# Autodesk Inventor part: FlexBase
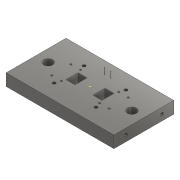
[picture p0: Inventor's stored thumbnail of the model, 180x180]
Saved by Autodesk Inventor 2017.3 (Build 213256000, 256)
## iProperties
Part Number: FlexBase
Material: ステンレス鋼
Document SubType Name: モデリング
Designer: kyushu-hep
Density: 8 g/cm^3
Appearance: 半つや出し
Sheet Metal Rule: Default
Mass: 5352.02 g
Surface Area: 367.335 cm^2
Volume: 277.307 cm^3
Author: kyushu-hep
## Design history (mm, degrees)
sketch "スケッチ1"
  geometry: L1 (-126, 0)-(126, 0) reference; L2 (0, -70)-(0, 70) reference; L3 (90, -50)-(-90, -50); L4 (-90, -50)-(-90, 50); L5 (-90, 50)-(90, 50); L6 (90, 50)-(90, -50); L7 (90, -50)-(-90, 50); L8 (-90, -50)-(90, 50); 1 further point
  constraints: 12 end point, 2 midpoint, 2 parallel, 1 horizontal, 1 perpendicular
  dimensions: "d0" = 180 distance of L4.end L5.end; "d1" = 100 distance of L3.end L4.end
extrude "押し出し1" new body sketch "スケッチ1" distance "d2" = 20; taper "d3" = 0 deg
sketch "スケッチ12"
  geometry: L1 (-90, 50)-(-90, -50) reference; L2 (-90, -50)-(90, -50) reference; C1 r 0.5 at (-5.05, 29.5); C2 r 0.5 at (5.05, 29.5); 1 further point
  constraints: 2 centre point
  dimensions: "d66" = 1 diameter of C1; "d67" = 1 diameter of C2; "d130" = 10.1 distance of C2.centre C1.centre; "d133" = 29.5 vertical distance of point (0, 0) C2.centre; "d134" = 5.05 horizontal distance of C1.centre point (0, 0)
extrude "押し出し9" join sketch "スケッチ12" distance "d72" = 10; taper "d73" = 0 deg
sketch "スケッチ18"
  geometry: L1 (-90, 50)-(-90, -50) reference; L2 (-15, -10)-(-30, -10); L3 (-30, -10)-(-30, 10); L4 (-30, 10)-(-15, 10); L5 (-15, 10)-(-15, -10); L6 (-15, -10)-(-30, 10); L7 (-30, -10)-(-15, 10); L8 (90, -50)-(90, 50) reference; L9 (15, -10)-(30, -10); L10 (30, -10)-(30, 10); L11 (30, 10)-(15, 10); L12 (15, 10)-(15, -10); L13 (15, -10)-(30, 10); L14 (30, -10)-(15, 10); L15 (-90, -50)-(90, -50) reference; 3 further points
  constraints: 24 end point, 4 midpoint, 4 parallel, 2 equal length, 2 horizontal, 2 perpendicular, 1 collinear
  dimensions: "d108" = 15 distance from line of point (0, 0) L5; "d109" = 20 distance of L4.end L2.start; "d135" = 10 distance from line of point (0, 0) L2; "d151" = 15 distance of L2.start L2.end; "d152" = 15 distance from line of L12 point (0, 0)
extrude "押し出し15" cut sketch "スケッチ18" distance "d111" = 30; taper "d112" = 0 deg
sketch "スケッチ22"
  geometry: 1 further point
sketch "スケッチ23"
  geometry: C1 r 7.5 at (-70, 0); C2 r 7.5 at (70, 0); 1 further point
  constraints: 2 centre point
  dimensions: "d181" = 15 diameter of C1; "d184" = 15 diameter of C2; "d200" = 0 vertical distance of point (0, 0) C1.centre; "d201" = 0 vertical distance of C2.centre point (0, 0); "d204" = 70 distance of point (0, 0) C1.centre; "d205" = 70 distance of C2.centre point (0, 0)
sketch "スケッチ24"
  geometry: C1 r 2.5 at (-35, 25); C2 r 2.5 at (35, 25); C3 r 2.5 at (-35, -25); C4 r 2.5 at (35, -25); 2 further points
  constraints: 4 centre point, 1 coincident
  dimensions: "d159" = 5 diameter of C1; "d160" = 25 vertical distance of C1.centre point (0, 0); "d161" = 35 horizontal distance of C1.centre point (0, 0); "d162" = 5 diameter of C2; "d163" = 35 horizontal distance of point (0, 0) C2.centre; "d164" = 25 vertical distance of C2.centre point (0, 0); "d165" = 5 diameter of C3; "d166" = 25 vertical distance of point (0, 0) C3.centre; "d167" = 35 horizontal distance of point (0, 0) C3.centre; "d168" = 5 diameter of C4; "d169" = 25 vertical distance of point (0, 0) C4.centre; "d170" = 35 horizontal distance of point (0, 0) C4.centre
extrude "押し出し19" cut sketch "スケッチ24" distance "d171" = 20; taper "d172" = 0 deg
feature "ねじ4" dims "d173" = 10, "d174" = 0
feature "ねじ5" dims "d175" = 10, "d176" = 0
feature "ねじ6" dims "d177" = 10, "d178" = 0
feature "ねじ7" dims "d179" = 10, "d180" = 0
sketch "スケッチ25"
  geometry: L1 (20, 20)-(-20, 20); L2 (-20, 20)-(-20, -20); L3 (-20, -20)-(20, -20); L4 (20, -20)-(20, 20); L5 (20, 20)-(-20, -20); L6 (-20, 20)-(20, -20); C1 r 1.5 at (-48, -16); C2 r 1.5 at (-48, 16); C3 r 1.5 at (-32, -16); C4 r 1.5 at (-32, 16); C5 r 1.5 at (-16, -16); C6 r 1.5 at (-16, 16); C7 r 1.5 at (0, -16); C8 r 1.5 at (0, 16); C9 r 1.5 at (16, -16); C10 r 1.5 at (16, 16); C11 r 1.5 at (32, -16); C12 r 1.5 at (32, 16); C13 r 1.5 at (48, -16); C14 r 1.5 at (48, 16); 2 further points
  constraints: 14 centre point, 12 end point, 2 horizontal, 2 midpoint, 2 parallel, 1 perpendicular, 1 vertical, 26 other
  dimensions: "d191" = 3 diameter of C1; "d192" = 48 horizontal distance of point (0, 0) C1.centre; "d193" = 16 vertical distance of point (0, 0) C1.centre; "d194" = 40 distance of L3.end L2.end; "d195" = 40 distance of L2.end L1.end; "d196" = 32 distance of C1.centre C2.centre; "d197" = 16 distance of C1.centre C3.centre
extrude "押し出し21" cut sketch "スケッチ25" distance "d198" = 20; taper "d199" = 0 deg
extrude "押し出し22" cut sketch "スケッチ23" distance "d202" = 10; taper "d203" = 0 deg
sketch "スケッチ26"
  geometry: C1 r 2.5 at (-10, 20); C2 r 2.5 at (-10, 80); 1 further point
  constraints: 2 centre point
  dimensions: "d206" = 5 diameter of C1; "d207" = 30 vertical distance of C1.centre point (0, 50); "d208" = 5 diameter of C2; "d209" = 30 vertical distance of C2.centre point (0, 50); "d210" = 10 horizontal distance of C1.centre point (0, 50); "d211" = 10 horizontal distance of C2.centre point (0, 50)
extrude "押し出し23" cut sketch "スケッチ26" distance "d212" = 10; taper "d213" = 0 deg
feature "ねじ8" dims "d214" = 10, "d215" = 0
feature "ねじ9" dims "d216" = 10, "d217" = 0
sketch "スケッチ27"
  geometry: C1 r 2.5 at (10, 80); C2 r 2.5 at (10, 20); 1 further point
  constraints: 2 centre point
  dimensions: "d218" = 5 diameter of C1; "d219" = 5 diameter of C2; "d220" = 30 vertical distance of point (0, 50) C1.centre; "d221" = 30 vertical distance of point (0, 50) C2.centre; "d222" = 10 horizontal distance of point (0, 50) C1.centre; "d223" = 10 horizontal distance of point (0, 50) C2.centre
extrude "押し出し24" cut sketch "スケッチ27" distance "d224" = 10; taper "d225" = 0 deg
feature "ねじ10" dims "d226" = 10, "d227" = 0
feature "ねじ11" dims "d228" = 10, "d229" = 0
node "ソリッド1"
other parameters: "Thickness" = 0.5, "Kファクター" = 4.4, "BendRadius" = 0.5 (= Thickness), "BendReliefWidth" = 0.5 (= Thickness), "BendReliefDepth" = 0.25 (= 0.5 x Thickness), "CornerReliefSize" = 2 (= 4 x Thickness), "SeamGap" = 0.01, "MinimumRemnant" = 1 (= 2 x Thickness), "TransitionRadius" = 0.5 (= BendRadius), "JacobiRadiusSize" = 0.5 (= Thickness), "GapSize" = 0.5 (= Thickness)
